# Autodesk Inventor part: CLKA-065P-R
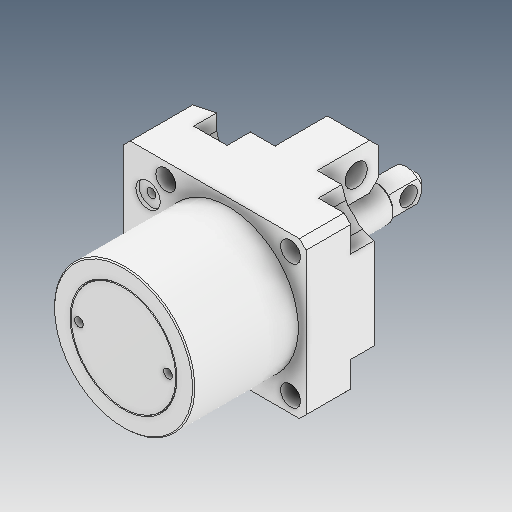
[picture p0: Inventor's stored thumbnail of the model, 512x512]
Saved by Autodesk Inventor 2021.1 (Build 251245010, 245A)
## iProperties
Created: 2021-06
Part Number: CLKA-065P-R
Material: Ogólny
Document SubType Name: Modeling
Designer: user
Density: 1 g/cm^3
Appearance: Domyślna
Author: user
Revision Number: ÈÎºÎ
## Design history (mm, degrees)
feature "Í¹Ì¨-À­Éì7"
node "Bryła1"
